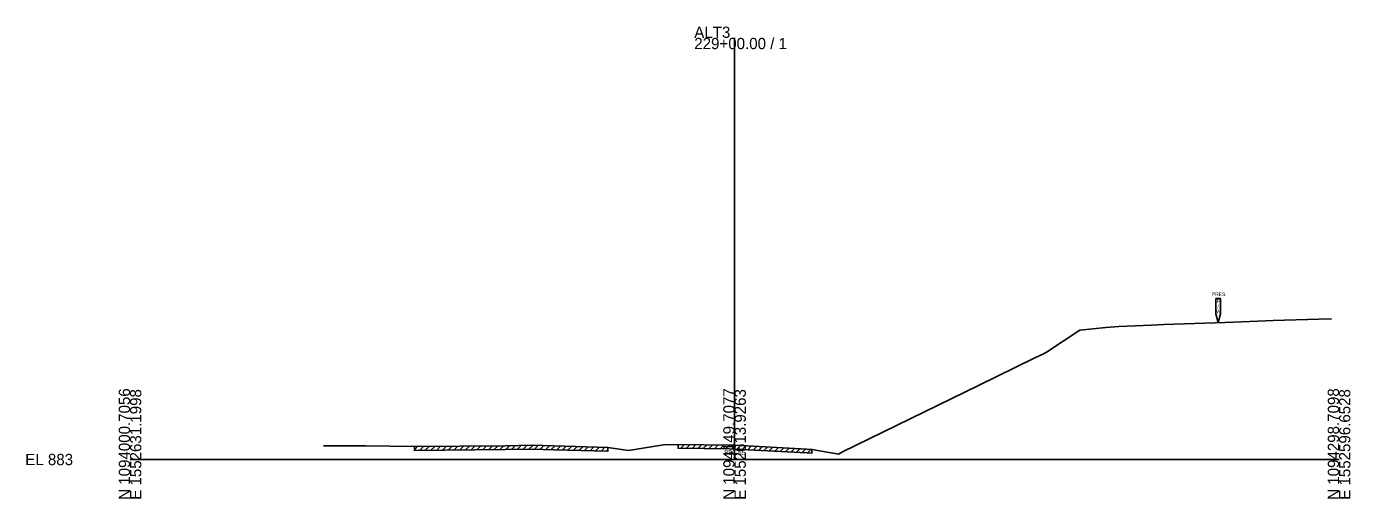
# Model space of a CAD drawing. Extents: x -26 to 1303, y -10 to 19582.
# Drawn here: x -25.7 to 302.8, y 2490.3 to 2607.6 of the extents above; entities that cross this region are included whole.
import ezdxf

# ---------------------------------------------------------------- set-up
doc = ezdxf.new("R2010")
doc.units = 0
for name, color, linetype in [('Default', 7, 'Continuous'), ('RD_GPK_XS_Cell', 7, 'Continuous'), ('RD_XS_ExGround', 7, 'Continuous'), ('RD_XS_ExPaveRet', 7, 'Continuous'), ('RD_XS_ExRW', 7, 'Continuous'), ('RD_XS_TX_Elev_EX', 7, 'Continuous')]:
    doc.layers.add(name, color=color, linetype=linetype)

msp = doc.modelspace()

# ---------------------------------------------------------------- linework, layer by layer
at = {"layer": 'RD_GPK_XS_Cell'}
for p, q in [((150, 2500), (150, 2604.72)), ((0, 2500), (150, 2500)), ((150, 2500), (300, 2500))]:
    msp.add_line(p, q, dxfattribs=at)
at = {"layer": 'RD_XS_ExGround'}
msp.add_lwpolyline([(48.02, 2503.39), (58.4, 2503.42), (70.56, 2503.22), (93.15, 2503.43), (99.76, 2503.53), (105.19, 2503.39), (118.59, 2503.01), (123.69, 2502.27), (132.41, 2503.61), (135.97, 2503.77), (148.66, 2503.57), (150.14, 2503.55), (167.97, 2502.57), (169.18, 2502.5), (175.41, 2501.4), (175.77, 2501.34), (176.75, 2501.89), (210.56, 2518.39), (224.35, 2525.15), (226.64, 2526.23), (227.38, 2526.69), (235.64, 2532.16), (242.15, 2532.75), (245.37, 2533.04), (253.48, 2533.38), (256.56, 2533.5), (271.62, 2534.05), (277.83, 2534.29), (283.63, 2534.51), (294.94, 2534.85), (298.09, 2534.91)], dxfattribs=at)
at = {"layer": 'RD_XS_ExPaveRet'}
for p, q in [((91.8, 2502.46), (92.76, 2503.42)), ((93.23, 2502.48), (94.19, 2503.44)), ((94.66, 2502.5), (95.63, 2503.46)), ((96.1, 2502.52), (97.07, 2503.49)), ((97.54, 2502.54), (98.5, 2503.51)), ((98.97, 2502.57), (99.93, 2503.52)), ((100.38, 2502.56), (101.31, 2503.49)), ((101.76, 2502.53), (102.69, 2503.45)), ((103.14, 2502.49), (104.07, 2503.42)), ((135.97, 2503.77), (135.97, 2502.77)), ((135.97, 2503.51), (136.22, 2503.77)), ((136.68, 2502.81), (137.62, 2503.75)), ((138.07, 2502.79), (139.01, 2503.73)), ((139.46, 2502.77), (140.4, 2503.7)), ((140.86, 2502.75), (141.79, 2503.68)), ((142.25, 2502.72), (143.18, 2503.66)), ((143.64, 2502.7), (144.58, 2503.64)), ((145.03, 2502.68), (145.97, 2503.62)), ((146.43, 2502.66), (147.36, 2503.59)), ((147.82, 2502.64), (148.75, 2503.57)), ((149.21, 2502.61), (150.14, 2503.54)), ((150.58, 2502.57), (151.48, 2503.47)), ((70.56, 2502.43), (71.35, 2503.23)), ((70.56, 2503.22), (70.56, 2502.22)), ((71.82, 2502.28), (72.78, 2503.24)), ((73.25, 2502.29), (74.2, 2503.25)), ((74.67, 2502.31), (75.63, 2503.27)), ((76.1, 2502.32), (77.06, 2503.28)), ((77.53, 2502.33), (78.49, 2503.29)), ((78.95, 2502.35), (79.91, 2503.3)), ((80.38, 2502.36), (81.34, 2503.32)), ((81.81, 2502.37), (82.77, 2503.33)), ((83.24, 2502.38), (84.2, 2503.34)), ((84.66, 2502.4), (85.62, 2503.36)), ((86.09, 2502.41), (87.05, 2503.37)), ((87.52, 2502.42), (88.48, 2503.38)), ((88.95, 2502.44), (89.9, 2503.4)), ((90.37, 2502.45), (91.33, 2503.41)), ((104.52, 2502.46), (105.45, 2503.38)), ((105.9, 2502.42), (106.82, 2503.34)), ((107.27, 2502.38), (108.2, 2503.3)), ((108.65, 2502.34), (109.57, 2503.26)), ((110.02, 2502.3), (110.95, 2503.23)), ((111.4, 2502.26), (112.32, 2503.19)), ((112.77, 2502.22), (113.7, 2503.15)), ((114.15, 2502.18), (115.07, 2503.11)), ((115.52, 2502.14), (116.45, 2503.07)), ((116.9, 2502.1), (117.82, 2503.03)), ((118.27, 2502.06), (118.59, 2502.38)), ((118.59, 2503), (118.59, 2502)), ((151.92, 2502.5), (152.82, 2503.4)), ((153.26, 2502.42), (154.16, 2503.32)), ((154.6, 2502.35), (155.5, 2503.25)), ((155.94, 2502.28), (156.84, 2503.18)), ((157.28, 2502.2), (158.18, 2503.1)), ((158.62, 2502.13), (159.52, 2503.03)), ((159.96, 2502.05), (160.87, 2502.95)), ((161.31, 2501.98), (162.21, 2502.88)), ((162.65, 2501.91), (163.55, 2502.81)), ((163.99, 2501.83), (164.89, 2502.73)), ((165.33, 2501.76), (166.23, 2502.66)), ((166.67, 2501.69), (167.57, 2502.59)), ((168.01, 2501.61), (168.91, 2502.51)), ((169.18, 2502.5), (169.18, 2501.5))]:
    msp.add_line(p, q, dxfattribs=at)
for points in [[(70.56, 2502.27), (93.11, 2502.47), (99.76, 2502.58), (105.22, 2502.44), (118.59, 2502.05)], [(135.97, 2502.82), (135.97, 2502.82), (148.65, 2502.62), (150.14, 2502.59), (167.95, 2501.62), (169.18, 2501.55)]]:
    msp.add_lwpolyline(points, dxfattribs=at)
at = {"layer": 'RD_XS_ExRW'}
msp.add_lwpolyline([(269.45, 2540.01), (270.55, 2540.01), (270.55, 2536.18), (270, 2533.99), (269.45, 2536.18)], close=True, dxfattribs=at)

# ---------------------------------------------------------------- texts
at = {"layer": 'Default'}
msp.add_text('-', height=0.0001, dxfattribs=at).set_placement((0, 2500))
at = {"layer": 'RD_GPK_XS_Cell'}
for s, p in [('ALT3', (140, 2604.72)), ('229+00.00 / 1', (140, 2601.92)), ('EL 883', (-26, 2498.6))]:
    msp.add_text(s, height=2.8, dxfattribs=at).set_placement(p)
for s, p in [('N 1094000.7056', (0, 2490)), ('E 1552631.1998', (2.8, 2490)), ('N 1094149.7077', (150, 2490)), ('E 1552613.9263', (152.8, 2490)), ('N 1094298.7098', (300, 2490)), ('E 1552596.6528', (302.8, 2490))]:
    msp.add_text(s, height=2.8, rotation=90, dxfattribs=at).set_placement(p)
at = {"layer": 'RD_XS_ExRW'}
for s, p in [('PRES.', (268.45, 2540.63)), ('R', (269.71, 2538.92)), ('W', (269.53, 2536.29)), ('/', (269.83, 2537.6))]:
    msp.add_text(s, height=0.875, dxfattribs=at).set_placement(p)
at = {"layer": 'RD_XS_TX_Elev_EX'}
msp.add_text('886.55', height=1.25, dxfattribs=at).set_placement((147.44, 2501.12))

doc.saveas('drawing.dxf')
